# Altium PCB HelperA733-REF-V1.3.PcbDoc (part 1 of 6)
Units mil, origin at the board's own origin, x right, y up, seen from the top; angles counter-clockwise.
Board outline 5905.51 x 4133.86 mil, 2 copper layers (Top, Bottom), stack 12.7 mil thick; 446 components, 341 nets, 1706 pads, 1667 vias.
Unrouted connection lines stored in the file: 1382.
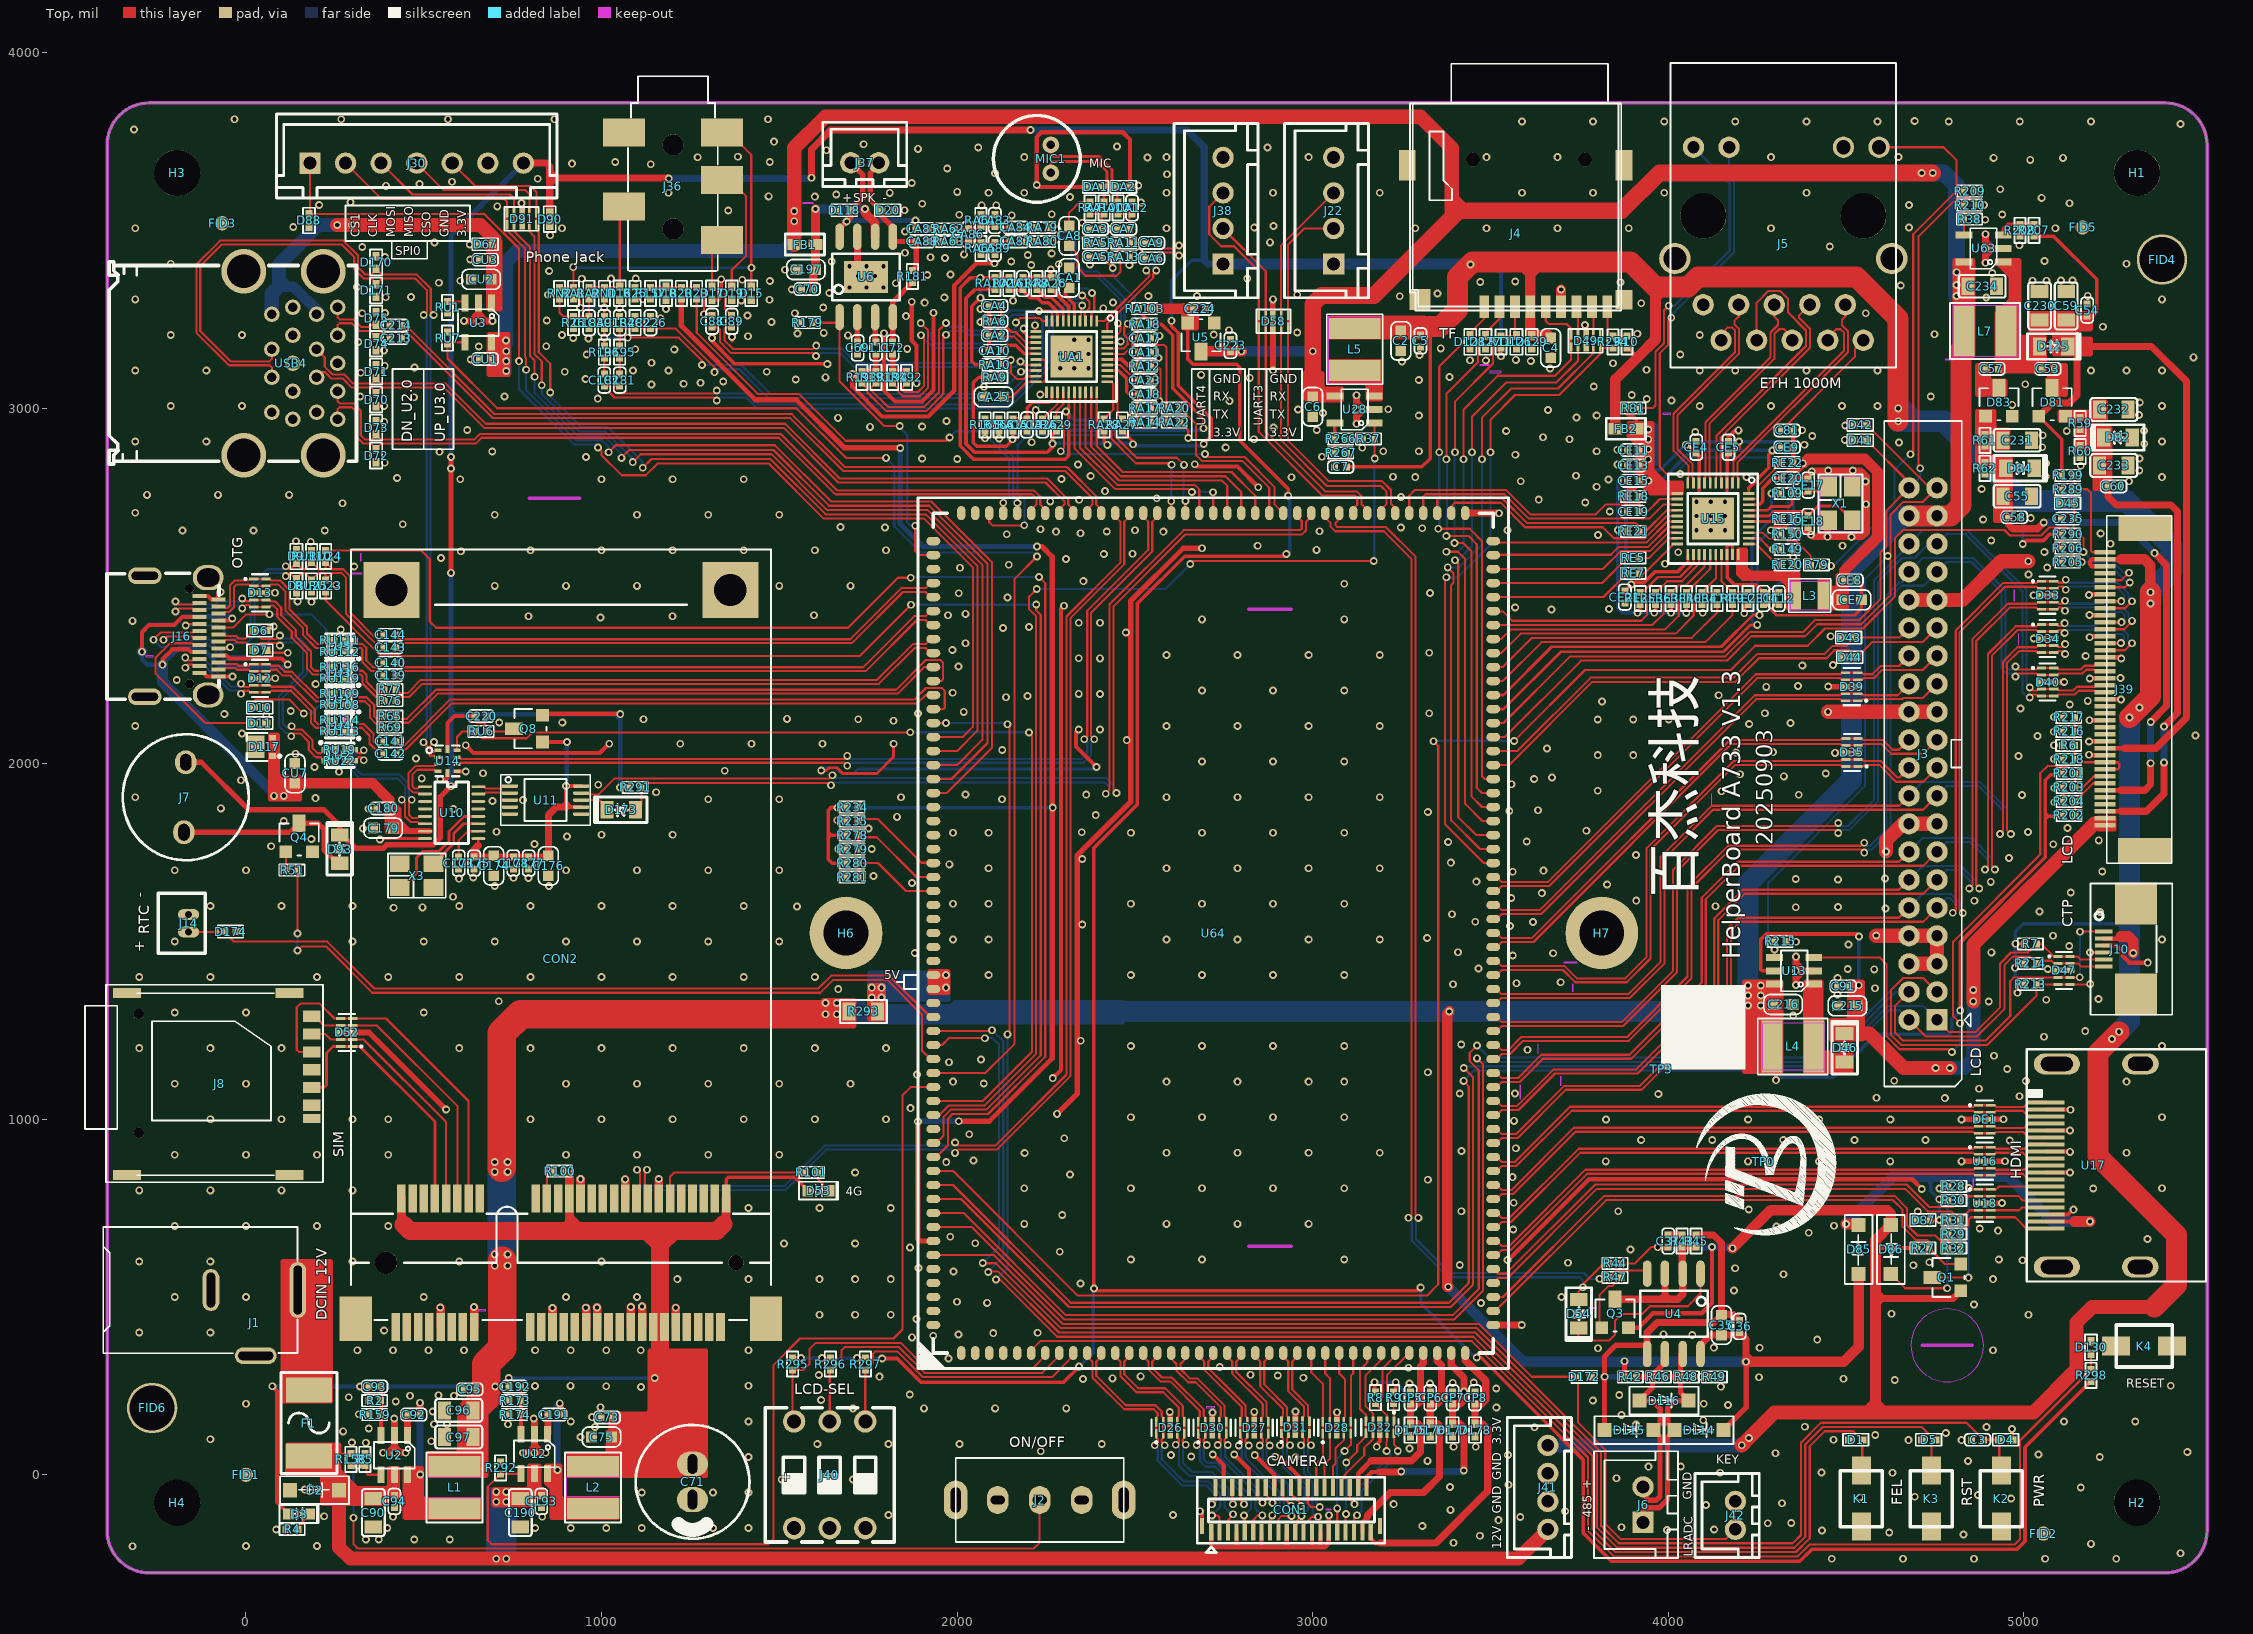
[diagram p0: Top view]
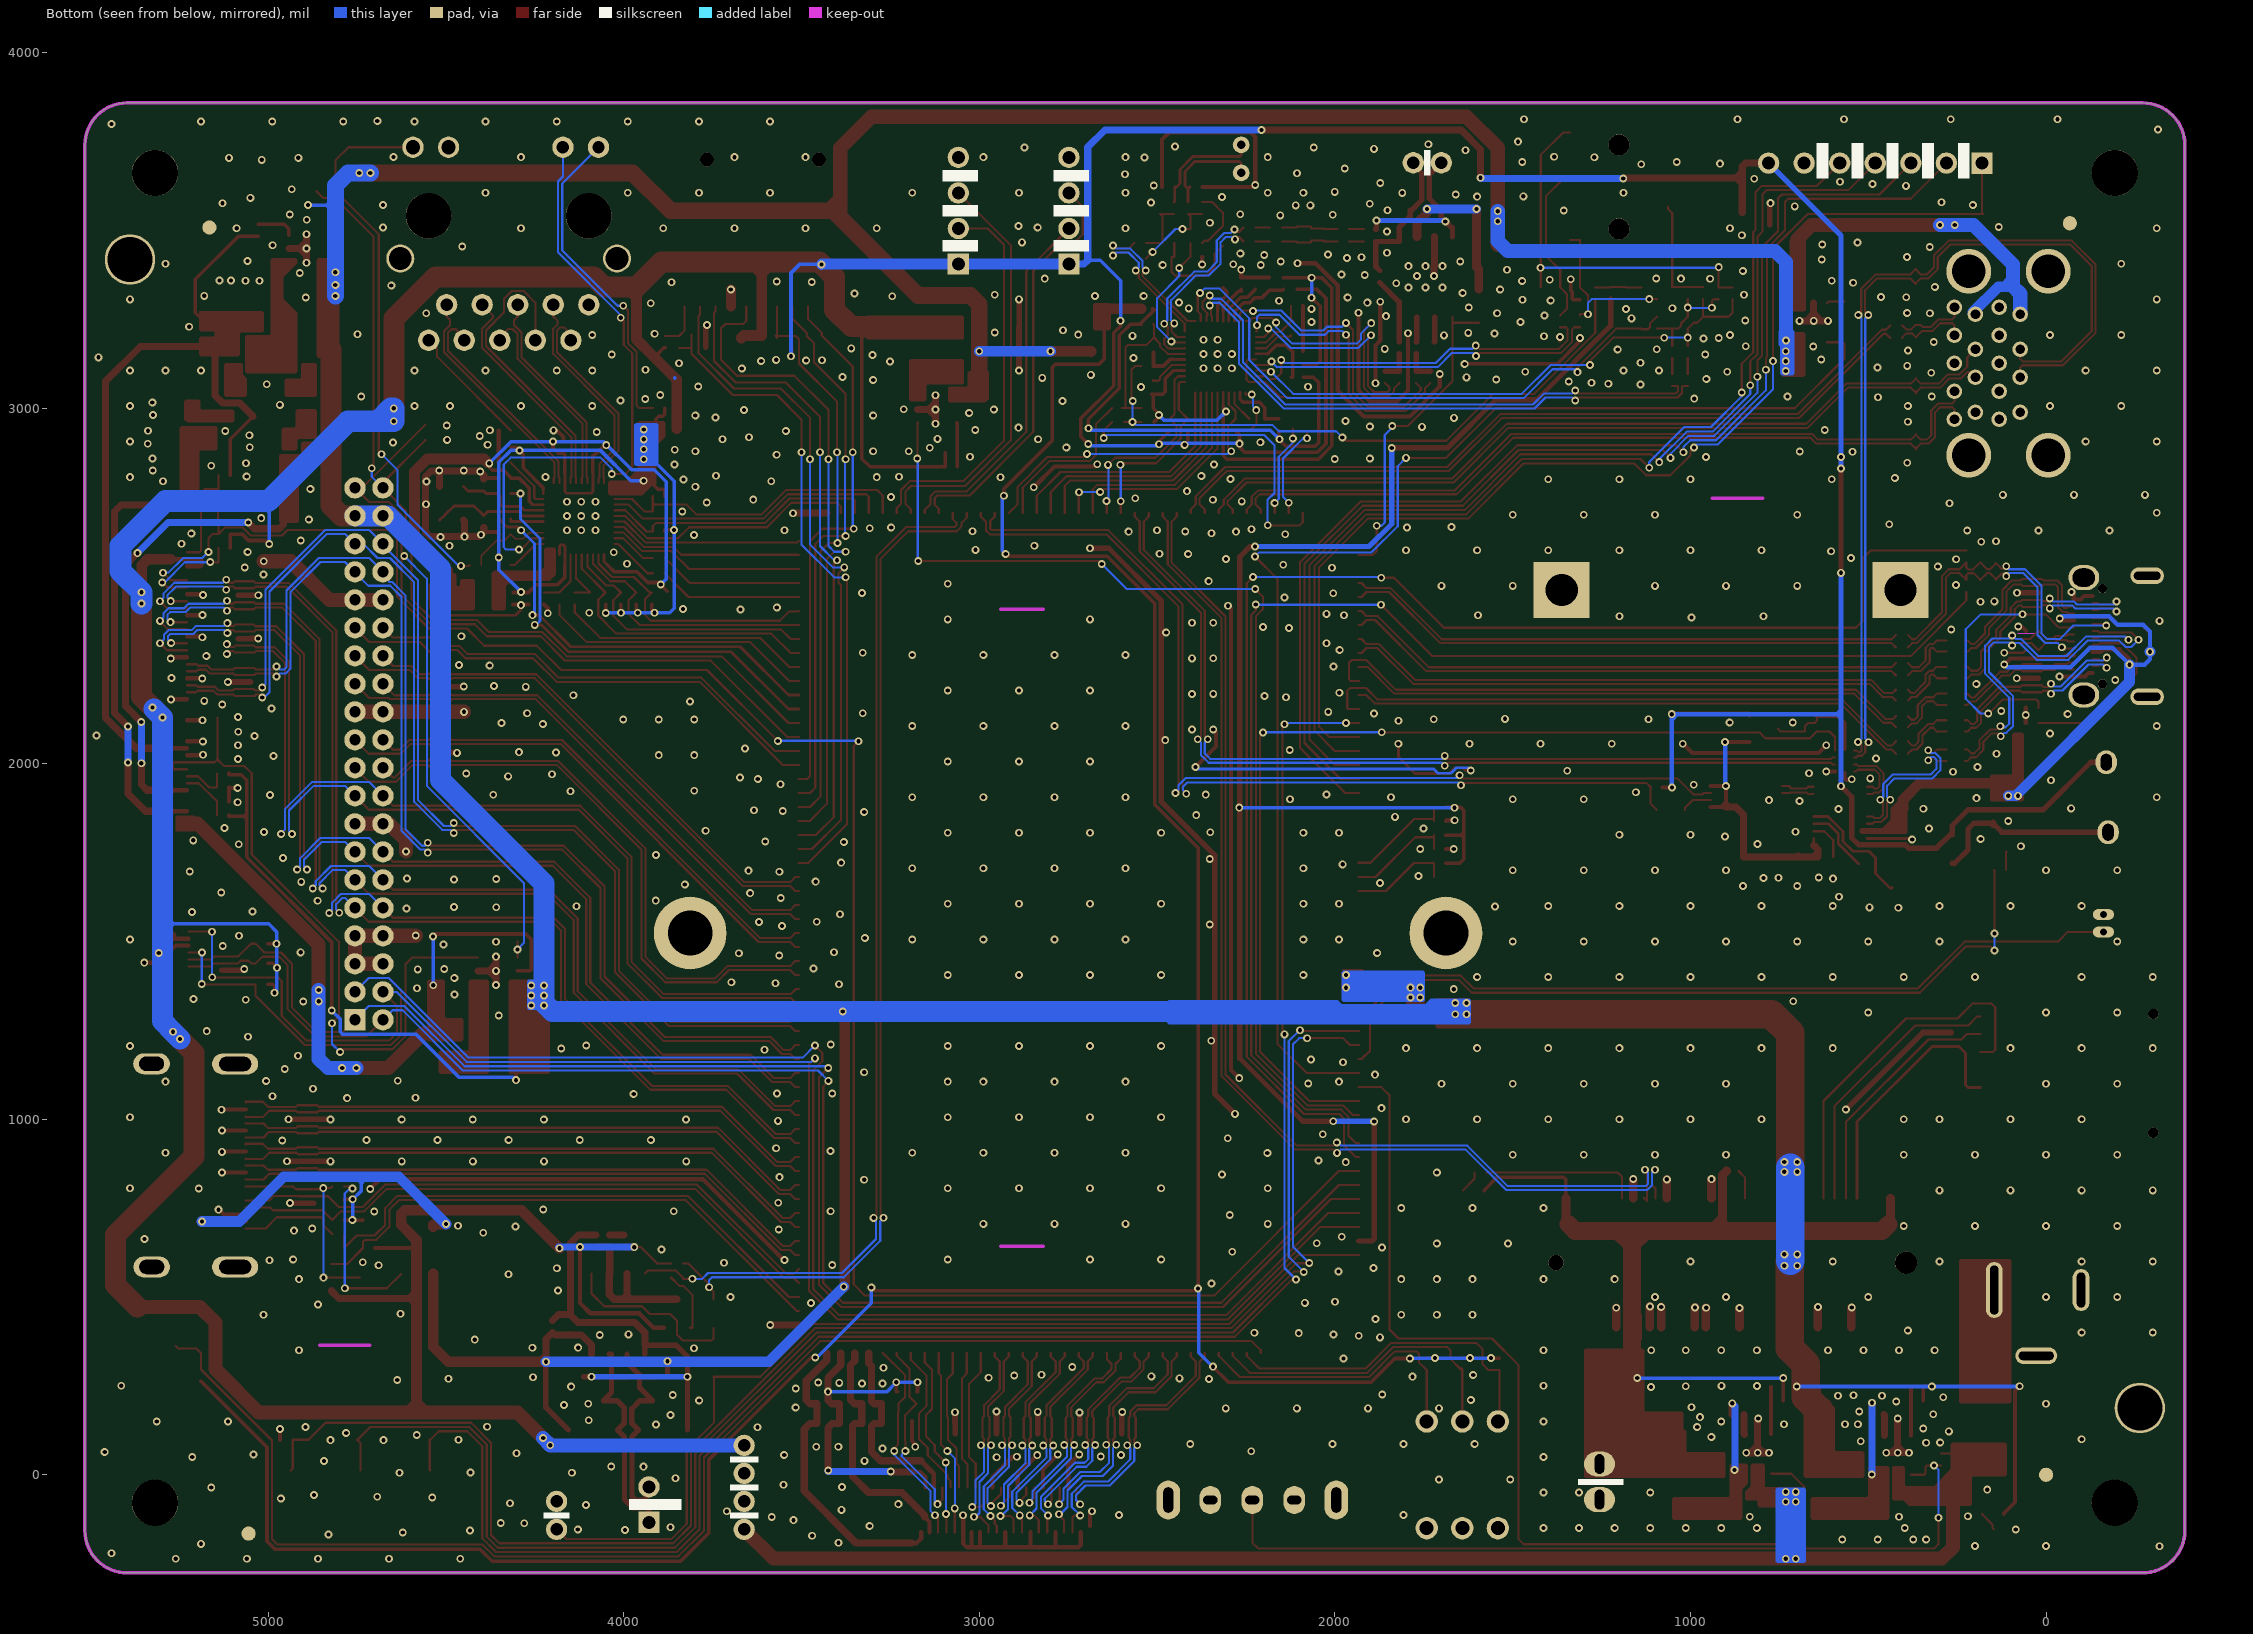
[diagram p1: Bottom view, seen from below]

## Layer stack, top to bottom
Solder Mask Top: solder mask 0.4, Solder Resist, Dk 3.5
Top: signal copper 1.35
Dielectric 1: dielectric 10, FR-4, Dk 4.3
Bottom: signal copper 1.35
Solder Mask Bottom: solder mask 0.4, Solder Resist, Dk 3.5

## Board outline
-390.17,3740.16 cw(c-272.06,3740.16) -272.06,3858.27 5397.23,3858.27 cw(c5397.23,3740.16) 5515.34,3740.16 5515.34,-157.48 cw(c5397.23,-157.48) 5397.23,-275.59 -272.06,-275.59 cw(c-272.06,-157.48) -390.17,-157.48

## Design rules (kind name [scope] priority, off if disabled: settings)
Clearance "Clearance - Net - 340_3V3" [InNet('340_3V3') OR InNet('LED1_AD1')] p1: gap=6 ignorepadtopadclearanceinfootprint=FALSE except(0: Arc-Hole Track-Hole SMDPad-Hole THPad-Hole Via-Hole Fill-Hole Poly-Hole Region-Hole Text-Hole; 10: Fill-Fill Fill-Poly Fill-Region Poly-Poly Poly-Region Region-Region Text-Text; 12: Arc-Fill Arc-Poly Arc-Region Track-Fill Track-Poly Track-Region SMDPad-Fill SMDPad-Poly SMDPad-Region THPad-Fill THPad-Poly THPad-Region Via-Fill Via-Poly Via-Region)
Clearance "Clearance - Net - GND" [InNet('GND')] p2: gap=6 ignorepadtopadclearanceinfootprint=FALSE except(0: Arc-Hole Track-Hole SMDPad-Hole THPad-Hole Via-Hole Fill-Hole Poly-Hole Region-Hole Text-Hole; 8: Arc-Fill Arc-Poly Arc-Region Track-Fill Track-Poly Track-Region SMDPad-Fill SMDPad-Poly SMDPad-Region THPad-Fill THPad-Poly THPad-Region Via-Fill Via-Poly Via-Region; 10: Fill-Fill Fill-Poly Fill-Region Poly-Poly Poly-Region Region-Region Text-Text)
Clearance "Clearance - Default - DEFAULT- SMD" [IsVia vs IsSMTPin] p3: gap=0 ignorepadtopadclearanceinfootprint=FALSE
Clearance "Clearance - Default - DEFAULT - Via" [IsVia vs IsVia] p4: gap=0 ignorepadtopadclearanceinfootprint=FALSE
Clearance "Clearance - Default - DEFAULT - Net" [All] p5: gap=6 ignorepadtopadclearanceinfootprint=FALSE except(0: Arc-Hole Track-Hole SMDPad-Hole THPad-Hole Via-Hole Fill-Hole Poly-Hole Region-Hole Text-Hole; 10: Fill-Fill Fill-Poly Fill-Region Poly-Poly Poly-Region Region-Region Text-Text)
ComponentClearance "ComponentClearance - Default - DEFAULT" [All] p1: gap=6 collisioncheckmode=3 verticalgap=10 showdistances=FALSE
FanoutControl Fanout_SOIC [IsSOIC] p1: bgadir=Out bgaviamode=Centered fanoutstyle=Auto fanoutdirection=Alternating viagrid=1 // Fanout_SOIC (Default Rule)
FanoutControl Fanout_Small [(CompPinCount < 5)] p2: bgadir=Out bgaviamode=Centered fanoutstyle=Auto fanoutdirection=OutThenIn viagrid=1 // Fanout_Small (Default Rule)
FanoutControl Fanout_LCC [IsLCC] p3: bgadir=Out bgaviamode=Centered fanoutstyle=Auto fanoutdirection=Alternating viagrid=1 // Fanout_LCC (Default Rule)
FanoutControl Fanout_BGA [IsBGA] p4: bgadir=Out bgaviamode=Centered fanoutstyle=Auto fanoutdirection=Alternating viagrid=1 // Fanout_BGA (Default Rule)
HoleToHoleClearance "HoleToHoleClearance - Default - DEFAULT" [All] p1: gap=6 allowstackedmicrovias=TRUE
Length "Length - NetClass - MLNetGroup4" [InNetClass('MLNetGroup4')] p1: maxlimit=18503.27 minlimit=0
Length "Default Length" [All] p2: maxlimit=50000 minlimit=0
MatchedLengths "MatchedLengths - NetClass - MLNetGroup4" [InNetClass('MLNetGroup4')] p1: tolerance=200 checknetsindiffpair=FALSE checkdiffpairvsdiffpair=TRUE checkxsignals=TRUE checkothers=TRUE
MaxMinImpedance "Default Impedance" [All] p1: minimum=50.00 maximum=150.0
ParallelSegment "Default Parallel Segment Same Layer" [All] p1: limit=1000 gap=200
ParallelSegment "Default Parallel Segment Adjasent" [All] p2: limit=1000 gap=200
PlaneConnect "Default PlaneConnect" [All] p1: planeconnectstyle=Relief reliefexpansion=20 reliefentries=0 reliefconductorwidth=15 reliefairgap=10
PolygonConnect "PolygonConnect - Default SMT" [IsSMTPin] p1: connectstyle=Relief reliefconductorwidth=10 reliefentries=4 polygonreliefangle="90 Angle" airgapwidth=10
PolygonConnect "PolygonConnect - Default Pad" [All] p2: connectstyle=Relief reliefconductorwidth=15 reliefentries=4 polygonreliefangle="45 Angle" airgapwidth=10
RoutingLayers "RoutingLayers - Default - DEFAULT" [All] p1: top layer_v5=TRUE bottom layer_v5=TRUE
RoutingPriority "RoutingPriority - Default - DEFAULT" [All] p1: routingpriority=3
RoutingTopology "Default Routing Topology" [All] p1: topology=Shortest
RoutingVias "RoutingVias - Default - DEFAULT" [All] p1: holewidth=12 width=22 viastyle="Through Hole" minholewidth=12 minwidth=22 maxholewidth=12 maxwidth=22
SMDToCorner "SMDToCorner - Default - DEFAULT" [All] p1: distance=0
SolderMaskExpansion [All] p1: expansion=4
Width "Width - Net - LED1_AD1" [InNet('LED1_AD1')] p1: maxlimit=200 minlimit=5 preferedwidth=5
Width "Width - Net - 340_3V3" [InNet('340_3V3')] p2: maxlimit=200 minlimit=5 preferedwidth=15
Width "Width - Net - GND" [InNet('GND')] p3: maxlimit=200 minlimit=5 preferedwidth=11.81
Width "Default Width" [All] p4: maxlimit=200 minlimit=6 preferedwidth=6
18 further rules are at their usual default settings.

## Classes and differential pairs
net class MLNetGroup4: LVDS0-D0N LVDS0-D0P LVDS0-D1N LVDS0-D1P LVDS0-D2N LVDS0-D2P
net class RoutingClass_9(RuleSet): 340_3V3 GND LED1_AD1

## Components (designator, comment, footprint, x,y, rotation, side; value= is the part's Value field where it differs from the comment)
C2 "C0603" C0603 3248.03,3188.98 r270 top
C3 "C0402" C0402 4870.08,98.43 r180 top
C4 "C0603" C0603 3669.29,3169.29 r90 top
C5 "C0402" C0402 3303.15,3188.98 r270 top
C6 "C0603" C0603 3000,3003.94 r270 top
C7 "C0402" C0402 3078.74,2834.65 r180 top
C35 "C0603" C0603 4149.61,421.26 r90 top
C36 "C0402" C0402 4200.79,417.32 r90 top
C37 "C0402" C0402 4000,657.48 r90 top
C53 "C0402" C0402 5067.91,3110.24 r180 top
C54 "C0402" C0402 5178.15,3275.59 r90 top
C55 "C0805" C0805 4981.3,2751.97 r0 top
C57 "C0402" C0402 4910.43,3110.24 r180 top
C58 "C0402" C0402 4973.42,2692.91 r0 top
C59 "C0805" C0805 5119.09,3287.4 r90 top
C60 "C0402" C0402 5252.95,2779.53 r0 top
C69 "C0402" C0402 1720.47,3169.29 r270 top
C70 "C0402" C0402 1578.74,3334.65 r180 top
C71 "RB.1$2F$.3" RB.1$2F$.3 1255.91,-19.68 r90 top
C72 "C0402" C0402 1818.9,3169.29 r270 top
C73 "C0402" C0402 1015.75,161.42 r180 top
C75 "C0603" C0603 1000,106.3 r180 top
C81 "C0402" C0402 4334.65,2937.01 r180 top
C88 "C0402" C0402 1311.02,3244.09 r270 top
C89 "C0402" C0402 1366.14,3244.09 r270 top
C90 "C0805" C0805 358.27,-106.3 r270 top
C91 "C0402" C0402 4492.13,1374.02 r180 top
C92 "C0402" C0402 472.44,169.29 r0 top
C93 "C0402" C0402 362.2,248.03 r0 top
C94 "C0402" C0402 417.32,-74.8 r270 top
C95 "C0402" C0402 629.92,240.16 r180 top
C96 "C0805" C0805 598.43,181.1 r180 top
C97 "C0805" C0805 598.43,106.3 r180 top
C111 "C0402" C0402 1771.65,3169.29 r270 top
C139 "C0402" C0402 405.51,2248.03 r180 top
C140 "C0402" C0402 405.51,2283.46 r180 top
C141 "C0402" C0402 405.51,2062.99 r180 top
C142 "C0402" C0402 405.51,2027.56 r180 top
C143 "C0402" C0402 405.51,2326.77 r180 top
C144 "C0402" C0402 405.51,2362.2 r180 top
C173 "C0402" C0402 598.43,1720.47 r270 top
C174 "C0603" C0603 696.85,1712.6 r270 top
C175 "C0402" C0402 641.73,1720.47 r270 top
C176 "C0603" C0603 850.39,1712.6 r270 top
C177 "C0402" C0402 795.28,1720.47 r270 top
C178 "C0402" C0402 751.97,1720.47 r270 top
C179 "C0603" C0603 385.83,1818.9 r180 top
C180 "C0402" C0402 385.83,1874.02 r180 top
C181 "C0402" C0402 1051.18,3078.74 r90 top
C182 "C0402" C0402 1007.87,3078.74 r90 top
C183 "C0402" C0402 964.57,3240.16 r270 top
C184 "C0402" C0402 1051.18,3240.16 r90 top
C190 "C0805" C0805 771.65,-106.3 r270 top
C191 "C0402" C0402 866.14,169.29 r0 top
C192 "C0402" C0402 755.91,248.03 r0 top
C193 "C0402" C0402 830.71,-74.8 r270 top
C197 "C0603" C0603 1574.8,3389.76 r180 top
C213 "C0402" C0402 421.38,3197.01 r180 top
C214 "C0402" C0402 421.38,3232.44 r180 top
C215 "C0603" C0603 4503.94,1318.9 r180 top
C216 "C0603" C0603 4322.83,1322.83 r0 top
C220 "C0402" C0402 661.42,2133.86 r0 top
C223 "C0402" C0402 2768.64,3176.34 r270 top
C224 "C0402" C0402 2682.02,3278.7 r180 top
C226 "C0402" C0402 1137.8,3240.16 r270 top
C230 "C0805" C0805 5044.29,3287.4 r90 top
C231 "C0805" C0805 4981.3,2909.45 r180 top
C232 "C0805" C0805 5252.95,2996.06 r0 top
C233 "C0805" C0805 5252.95,2838.58 r0 top
C234 "C0805" C0805 4882.87,3342.52 r0 top
C235 "C0402" C0402 5123.03,2688.98 r0 top
CA1 "C0603" C0603 2314.96,3366.14 r270 top
CA2 "C0402" C0402 2106.3,3204.72 r180 top
CA3 "C0402" C0402 2389.76,3503.94 r0 top
CA4 "C0402" C0402 2106.3,3287.4 r0 top
CA5 "C0402" C0402 2389.76,3425.2 r0 top
CA6 "C0402" C0402 2547.24,3421.26 r180 top
CA7 "C0402" C0402 2468.5,3503.94 r0 top
CA8 "C0603" C0603 2314.96,3484.25 r270 top
CA9 "C0402" C0402 2547.24,3464.57 r180 top
CA10 "C0402" C0402 2106.3,3161.42 r180 top
CA11 "C0402" C0402 2527.56,3157.48 r0 top
CA12 "C0402" C0402 2492.13,3562.99 r90 top
CA13 "C0402" C0402 2196.85,2952.76 r270 top
CA14 "C0402" C0402 2185.04,3350.39 r90 top
CA17 "C0402" C0402 2527.56,3196.85 r0 top
CA18 "C0402" C0402 2527.56,3039.37 r180 top
CA23 "C0402" C0402 2527.56,3078.74 r0 top
CA25 "C0603" C0603 2102.36,3031.5 r180 top
CA26 "C0402" C0402 2240.16,2952.76 r270 top
CA83 "C0402" C0402 2106.3,3527.56 r270 top
CA84 "C0402" C0402 2165.35,3507.87 r0 top
CA85 "C0402" C0402 1901.57,3503.94 r0 top
CA86 "C0402" C0402 2031.5,3488.19 r270 top
CA87 "C0402" C0402 2165.35,3468.5 r0 top
CA88 "C0402" C0402 1901.57,3468.5 r0 top
CA89 "C0402" C0402 2106.3,3448.82 r270 top
CA91 "C0402" C0402 1007.87,3240.16 r270 top
CE4 "C0402" C0402 4078.74,2889.76 r270 top
CE5 "C0402" C0402 4169.29,2889.76 r270 top
CE7 "C0603" C0603 4515.75,2460.63 r180 top
CE8 "C0402" C0402 4511.81,2515.75 r180 top
CE9 "C0402" C0402 4334.65,2889.76 r180 top
CE11 "C0402" C0402 3901.57,2881.89 r0 top
CE12 "C0402" C0402 4311.02,2464.57 r90 top
CE13 "C0402" C0402 3901.57,2838.58 r0 top
CE14 "C0402" C0402 4267.72,2464.57 r90 top
CE15 "C0402" C0402 3901.57,2795.28 r0 top
CE17 "C0402" C0402 4393.7,2783.46 r270 top
CE18 "C0402" C0402 4393.7,2681.1 r90 top
CE19 "C0402" C0402 3901.57,2708.66 r0 top
CE20 "C0402" C0402 4334.65,2803.15 r180 top
CE21 "C0402" C0402 3877.95,2468.5 r90 top
CON1 "FH35C-39S-0.3SHW" FH35C-39S-0.3SHW 2939.1,-102.33 r0 top
CON2 "MINI_PCIEX1-52P-5.2H" MINI_PCIEX1-52P-5.2H 885.83,1627.03 r0 top
CP5 "C0402" C0402 3275.59,216.54 r90 top
CP6 "C0402" C0402 3330.71,216.54 r90 top
CP7 "C0402" C0402 3393.7,216.54 r90 top
CP8 "C0402" C0402 3456.69,216.54 r90 top
CU1 "C0402" C0402 673.23,3137.8 r0 top
CU2 "C0603" C0603 661.42,3362.2 r0 top
CU3 "C0402" C0402 673.23,3417.32 r0 top
CU7 "C0603" C0603 137.8,1972.44 r90 top
D1 "ESD0402" ESD0402 4527.56,98.43 r180 top
D2 "SOD123" SOD123 192.91,-43.31 r0 top
D3 "D0603" D0603 149.61,-110.24 r0 top
D4 "ESD0402" ESD0402 4948.82,98.43 r180 top
D5 "ESD0402" ESD0402 4732.28,98.43 r0 top
D6 "ESD0402" ESD0402 39.37,2374.02 r0 top
D7 "ESD0402" ESD0402 39.37,2318.9 r0 top
D8 "ESD0402" ESD0402 141.73,2500 r270 top
D9 "ESD0402" ESD0402 141.73,2582.68 r90 top
D10 "ESD0402" ESD0402 39.37,2157.48 r0 top
D11 "ESD0402" ESD0402 39.37,2114.17 r0 top
D12 "DFN2510-10_L2.5-W1.0-P0.50-BL" DFN2510-10_L2.5-W1.0-P0.50-BL 39.37,2240.16 r270 top
D13 "DFN2510-10_L2.5-W1.0-P0.50-BL" DFN2510-10_L2.5-W1.0-P0.50-BL 39.37,2480.32 r270 top
D15 "ESD0402" ESD0402 1421.26,3322.83 r90 top
D16 "ESD0402" ESD0402 1051.18,3322.83 r90 top
D17 "ESD0402" ESD0402 1311.02,3322.83 r90 top
D18 "ESD0402" ESD0402 1181.1,3322.83 r90 top
D19 "ESD0402" ESD0402 1366.14,3322.83 r90 top
D20 "ESD0402" ESD0402 1805.07,3556.24 r180 top
D26 "DFN2510-10_L2.5-W1.0-P0.50-BL" DFN2510-10_L2.5-W1.0-P0.50-BL 2599.43,132.32 r0 top
D27 "DFN2510-10_L2.5-W1.0-P0.50-BL" DFN2510-10_L2.5-W1.0-P0.50-BL 2835.65,132.32 r0 top
D28 "DFN2510-10_L2.5-W1.0-P0.50-BL" DFN2510-10_L2.5-W1.0-P0.50-BL 3067.94,132.32 r0 top
D30 "DFN2510-10_L2.5-W1.0-P0.50-BL" DFN2510-10_L2.5-W1.0-P0.50-BL 2717.54,132.32 r0 top
D31 "DFN2510-10_L2.5-W1.0-P0.50-BL" DFN2510-10_L2.5-W1.0-P0.50-BL 2951.48,133.21 r0 top
D32 "DFN2510-10_L2.5-W1.0-P0.50-BL" DFN2510-10_L2.5-W1.0-P0.50-BL 3188.98,133.86 r180 top
D33 "DFN2510-10_L2.5-W1.0-P0.50-BL" DFN2510-10_L2.5-W1.0-P0.50-BL 5066.93,2473.73 r270 top
D34 "DFN2510-10_L2.5-W1.0-P0.50-BL" DFN2510-10_L2.5-W1.0-P0.50-BL 5066.93,2351.69 r270 top
D35 "DFN2510-10_L2.5-W1.0-P0.50-BL" DFN2510-10_L2.5-W1.0-P0.50-BL 4516.73,2031.5 r90 top
D39 "DFN2510-10_L2.5-W1.0-P0.50-BL" DFN2510-10_L2.5-W1.0-P0.50-BL 4515.75,2216.54 r90 top
D40 "DFN2510-10_L2.5-W1.0-P0.50-BL" DFN2510-10_L2.5-W1.0-P0.50-BL 5066.93,2229.64 r270 top
D41 "ESD0402" ESD0402 4540.35,2909.45 r180 top
D42 "ESD0402" ESD0402 4540.35,2952.76 r180 top
D43 "ESD0402" ESD0402 4507.87,2354.33 r180 top
D44 "ESD0402" ESD0402 4510.9,2299.12 r180 top
D45 "ESD0402" ESD0402 5123.03,2732.28 r180 top
D46 "SOD323" SOD323 4496.06,1200.79 r90 top
D47 "DFN2510-10_L2.5-W1.0-P0.50-BL" DFN2510-10_L2.5-W1.0-P0.50-BL 5112.97,1418.57 r270 top
D49 "RCLAMP0524P" RCLAMP0524P 3767.72,3188.98 r180 top
D52 "DFN2510-10_L2.5-W1.0-P0.50-BL" DFN2510-10_L2.5-W1.0-P0.50-BL 283.46,1244.09 r90 top
D53 "D0603" D0603 1610.24,799.21 r0 top
D54 "SOD323" SOD323 3748.03,452.76 r270 top
D58 "RCLAMP0524P" RCLAMP0524P 2889.76,3244.09 r0 top
D67 "ESD0402" ESD0402 673.23,3460.63 r0 top
D70 "ESD0402" ESD0402 366.26,3023.78 r270 top
D71 "ESD0402" ESD0402 366.26,3102.52 r90 top
D72 "ESD0402" ESD0402 366.26,2866.3 r270 top
D73 "ESD0402" ESD0402 366.26,2945.04 r90 top
D74 "ESD0402" ESD0402 366.26,3181.26 r270 top
D75 "ESD0402" ESD0402 366.26,3252.13 r90 top
D81 "SOT23" SOT23 5079.72,3015.75 r0 top
D82 "D0805" D0805 5264.76,2917.32 r180 top
D83 "SOT23" SOT23 4930.12,3015.75 r0 top
D84 "D0805" D0805 4989.17,2830.71 r0 top
D85 "SOD123" SOD123 4535.43,633.86 r90 top
D86 "SOD123" SOD123 4625.98,633.86 r270 top
D87 "ESD0402" ESD0402 4716.54,716.54 r180 top
D88 "ESD0402" ESD0402 177.17,3527.56 r270 top
D90 "ESD0402" ESD0402 854.33,3531.5 r270 top
D91 "RCLAMP0524P" RCLAMP0524P 775.41,3532.11 r180 top
D93 "SOD323" SOD323 263.78,1759.84 r90 top
D114 "SOD123" SOD123 4086.61,125.98 r0 top
D115 "SOD123" SOD123 3889.76,125.98 r0 top
D116 "SOD123" SOD123 3988.19,208.66 r0 top
D117 "DFN-3_2X2" DFN-3_2X2 51.18,2047.24 r0 top
D118 "ESD0402" ESD0402 1683.02,3556.24 r0 top
D125 "D0805" D0805 5083.66,3173.23 r0 top
D126 "ESD0402" ESD0402 3572.95,3186.09 r90 top
D127 "ESD0402" ESD0402 3486.34,3186.09 r90 top
D128 "ESD0402" ESD0402 3443.03,3186.09 r90 top
D129 "ESD0402" ESD0402 3616.26,3186.09 r90 top
D130 "ESD0402" ESD0402 5188.98,358.27 r90 top
D170 "ESD0402" ESD0402 366.26,3409.61 r90 top
D171 "ESD0402" ESD0402 366.26,3330.87 r270 top
D172 "ESD0402" ESD0402 3763.78,275.59 r180 top
D173 "SOD323" SOD323 1055.12,1870.08 r180 top
D174 "ESD0402" ESD0402 -43.31,1527.56 r180 top
D175 "ESD0402" ESD0402 3275.59,125.98 r90 top
D176 "ESD0402" ESD0402 3330.71,125.98 r90 top
D177 "ESD0402" ESD0402 3393.7,125.98 r90 top
D178 "ESD0402" ESD0402 3456.69,125.98 r90 top
DA1 "ESD0402" ESD0402 2389.76,3622.05 r0 top
DA2 "ESD0402" ESD0402 2468.5,3622.05 r180 top
DE1 "DFN2510-10_L2.5-W1.0-P0.50-BL" DFN2510-10_L2.5-W1.0-P0.50-BL 4889.76,1000 r270 top
F1 "F1812" F1812 177.17,145.67 r270 top
FB1 "L0603" L0603 1602.36,3460.63 r180 top
FB2 "L0603" L0603 3850.39,2940.94 r0 top
FID1 "MARK" MARK 0,0 r270 top
FID2 "MARK" MARK 5055.12,-165.35 r0 top
FID3 "MARK" MARK -66.93,3519.69 r0 top
FID4 "DVE" DVE 5388.69,3417.75 r0 top
FID5 "MARK" MARK 5165.35,3507.87 r0 top
FID6 "DVE" DVE -263.84,188.01 r0 top
H1 "DVA" DVA 5318.49,3661.42 r0 top
H2 "DVA" DVA 5318.49,-78.74 r0 top
H3 "DVA" DVA -193.32,3661.42 r0 top
H4 "DVA" DVA -193.32,-78.74 r0 top
H6 "DV" DV 1687.91,1523.62 r0 top
H7 "DV" DV 3813.29,1523.62 r0 top
J1 "DC470" DC470 -98.43,519.69 r0 top
J2 "SS-12F44(1P2T)" SS-12F44(1P2T) 2232.28,-70.87 r0 top
J3 "HDR2X20$2F$2.0" HDR2X20$2F$2.0 4755.91,1279.53 r90 top
J4 "TF_PUSH1" TF_PUSH1 3570.87,3570.87 r0 top
J5 "HY911130A" HY911130A 4548.61,3190.72 r0 top
J6 "XH-2.54-2P" XH-2.54-2P 3929.13,-133.86 r90 top
J7 "BEEP_9042" BEEP_9042 -169.29,1905.51 r270 top
J8 "NANO-SIM-7P" NANO-SIM-7P -86.61,1098.43 r270 top
J10 "FPC_0.5_6P_DOWN" FPC_0.5_6P_DOWN 5224.41,1527.56 r270 top
J14 "MX1.25-2P" MX1.25-2P -161.42,1551.18 r270 top
J16 "USB-C-SMD-24P" USB-C-SMD-24P -181.1,2358.27 r270 top
J22 "XH-2.54-4P" XH-2.54-4P 3059.06,3555.12 r270 top
J30 "XH-2.54-7P" XH-2.54-7P 480.31,3688.98 r180 top
J36 "PJ327F" PJ327F 1082.68,3858.27 r270 top
J37 "PH-2.0-2P" PH-2.0-2P 1700.81,3689.85 r0 top
J38 "XH-2.54-4P" XH-2.54-4P 2748.03,3555.12 r270 top
J39 "FPC40-0.5MM-UP" FPC40-0.5MM-UP 5208.66,1826.77 r90 top
J40 "SW-TH-DSWB03LHGET" SW-TH-DSWB03LHGET 1641.73,0 r0 top
J41 "PH-2.0-4P" PH-2.0-4P 3661.42,-153.54 r90 top
J42 "PH-2.0-2P" PH-2.0-2P 4188.98,-153.54 r90 top
K1 "KEY_3X4" KEY_3X4 4543.31,-66.93 r270 top
K2 "KEY_3X4" KEY_3X4 4937.01,-66.93 r90 top
K3 "KEY_3X4" KEY_3X4 4740.16,-66.93 r90 top
K4 "KEY_3X4" KEY_3X4 5338.58,362.2 r0 top
L1 "4018" 4018 586.61,-35.43 r90 top
L2 "4018" 4018 976.38,-35.43 r90 top
L3 "SML2520_1P2H$2F$4" SML2520_1P2H$2F$4 4397.64,2472.44 r270 top
L4 "4018" 4018 4350.39,1204.72 r0 top
L5 "4018" 4018 3118.11,3165.35 r90 top
L7 "4018" 4018 4890.75,3216.54 r0 top
LU1 "0805" 0805 263.78,2181.1 r90 top
LU2 "0805" 0805 263.78,2023.62 r270 top
LU3 "0805" 0805 263.78,2255.91 r90 top
LU4 "0805" 0805 263.78,2106.3 r90 top
LU5 "0805" 0805 263.78,2330.71 r90 top
MIC1 "MIC6050" MIC6050 2224.41,3700.79 r0 top
Q1 "SOT23" SOT23 4783.46,555.12 r90 top
Q3 "SOT23" SOT23 3850.39,452.76 r0 top
Q4 "SOT23" SOT23 149.61,1791.34 r0 top
Q8 "SOT23" SOT23 795.28,2098.43 r90 top
R2 "R0402" R0402 362.2,208.66 r0 top
R4 "R0402" R0402 129.92,-153.54 r0 top
R5 "R0402" R0402 334.65,43.31 r90 top
R6 "R0402" R0402 5125.98,2051.18 r180 top
R7 "R0402" R0402 5018.48,1493.37 r180 top
R8 "R0402" R0402 3176.54,216.76 r270 top
R9 "R0402" R0402 3227.72,216.76 r270 top
R10 "R0402" R0402 3883.97,3186.09 r90 top
R11 "R0402" R0402 3529.64,3186.09 r90 top
R20 "R0402" R0402 1224.41,3322.83 r90 top
R23 "R0402" R0402 1267.72,3322.83 r90 top
R25 "R0402" R0402 1094.49,3322.83 r90 top
R26 "R0402" R0402 921.26,3240.16 r270 top
R27 "R0402" R0402 4716.54,637.8 r180 top
R28 "R0402" R0402 4803.15,811.02 r0 top
R29 "R0402" R0402 4803.15,677.17 r0 top
R30 "R0402" R0402 4803.15,771.65 r180 top
R31 "R0402" R0402 4803.15,716.54 r180 top
R32 "R0402" R0402 4803.15,637.8 r0 top
R37 "R0402" R0402 3157.48,2913.39 r0 top
R38 "R0402" R0402 4847.44,3531.5 r180 top
R42 "R0402" R0402 3893.7,275.59 r0 top
R43 "R0402" R0402 4039.37,657.48 r270 top
R44 "R0402" R0402 3850.39,594.49 r0 top
R45 "R0402" R0402 4078.74,657.48 r90 top
R46 "R0402" R0402 3972.44,275.59 r180 top
R47 "R0402" R0402 3850.39,555.12 r180 top
R48 "R0402" R0402 4051.18,275.59 r180 top
R49 "R0402" R0402 4129.92,275.59 r0 top
R51 "R0402" R0402 129.92,1700.79 r180 top
R59 "R0402" R0402 5158.46,2956.69 r270 top
R60 "R0402" R0402 5158.46,2877.95 r90 top
R61 "R0402" R0402 4890.75,2909.45 r270 top
R62 "R0402" R0402 4890.75,2830.71 r90 top
R65 "R0402" R0402 405.51,2133.86 r180 top
R69 "R0402" R0402 405.51,2102.36 r180 top
R76 "R0402" R0402 405.51,2177.17 r180 top
R77 "R0402" R0402 405.51,2208.66 r180 top
R79 "R0402" R0402 4417.32,2559.06 r180 top
R81 "R0402" R0402 3901.57,3000 r180 top
R100 "R0402" R0402 881.89,854.33 r0 top
R101 "R0402" R0402 1590.55,850.39 r0 top
R109 "R0402" R0402 4334.65,2759.84 r0 top
R149 "R0402" R0402 4334.65,2602.36 r180 top
R150 "R0402" R0402 4334.65,2645.67 r180 top
R157 "R0402" R0402 1137.8,3322.83 r270 top
R158 "R0402" R0402 295.28,43.31 r270 top
R159 "R0402" R0402 362.2,169.29 r180 top
R165 "R0402" R0402 2078.74,2952.76 r270 top
R166 "R0402" R0402 2118.11,2952.76 r270 top
R173 "R0402" R0402 755.91,208.66 r0 top
R174 "R0402" R0402 755.91,169.29 r180 top
R179 "R0402" R0402 1578.74,3240.16 r0 top
R181 "R0402" R0402 1874.02,3370.08 r90 top
R191 "R0402" R0402 1771.65,3086.61 r90 top
R192 "R0402" R0402 1858.27,3086.61 r90 top
R193 "R0402" R0402 1732.28,3086.61 r90 top
R194 "R0402" R0402 1818.9,3086.61 r90 top
R195 "R0402" R0402 1051.18,3157.48 r90 top
R196 "R0402" R0402 1007.87,3157.48 r90 top
R199 "R0402" R0402 5123.03,2811.02 r0 top
R201 "R0402" R0402 5126.97,1972.44 r0 top
R202 "R0402" R0402 5126.97,1854.33 r0 top
R203 "R0402" R0402 5126.97,1933.07 r180 top
R204 "R0402" R0402 5126.97,1893.7 r180 top
R205 "R0402" R0402 5123.03,2566.93 r180 top
R206 "R0402" R0402 5123.03,2606.3 r0 top
R207 "R0402" R0402 5028.54,3500 r270 top
R208 "R0402" R0402 4989.17,3500 r270 top
R209 "R0402" R0402 4847.44,3610.24 r180 top
R210 "R0402" R0402 4847.44,3570.87 r0 top
R213 "R0402" R0402 5018.48,1379.2 r180 top
R214 "R0402" R0402 5018.48,1438.25 r180 top
R215 "R0402" R0402 4314.96,1500 r0 top
R216 "R0402" R0402 5125.98,2090.55 r180 top
R217 "R0402" R0402 5125.98,2129.92 r180 top
R218 "R0402" R0402 5125.98,2011.81 r180 top
R234 "R0402" R0402 1704.72,1877.95 r0 top
R235 "R0402" R0402 1704.72,1838.58 r180 top
R266 "R0402" R0402 3078.74,2913.39 r0 top
R267 "R0402" R0402 3078.74,2874.02 r180 top
R278 "R0402" R0402 1704.72,1799.21 r0 top
R279 "R0402" R0402 1704.72,1759.84 r180 top
R280 "R0402" R0402 1704.72,1720.47 r0 top
R281 "R0402" R0402 1704.72,1681.1 r180 top
R282 "R0402" R0402 1094.49,3240.16 r90 top
R289 "R0402" R0402 5123.03,2771.65 r180 top
R290 "R0402" R0402 5123.03,2645.67 r0 top
R291 "R0402" R0402 1094.49,1933.07 r180 top
R292 "R0402" R0402 716.54,19.69 r90 top
R293 "R0805" R0805 1736.22,1303.15 r0 top
R294 "R0402" R0402 3844.6,3186.09 r90 top
R295 "R0402" R0402 1537.49,311.58 r270 top
R296 "R0402" R0402 1643.79,311.58 r270 top
R297 "R0402" R0402 1742.21,311.58 r270 top
R298 "R0402" R0402 5188.98,279.53 r90 top
RA1 "R0402" R0402 921.26,3322.83 r90 top
RA2 "R0402" R0402 964.57,3322.83 r90 top
RA5 "R0402" R0402 2389.76,3464.57 r0 top
RA6 "C0402" C0402 2106.3,3244.09 r0 top
RA7 "R0402" R0402 2374.02,3562.99 r270 top
RA8 "R0402" R0402 2224.41,3350.39 r90 top
RA9 "R0402" R0402 2106.3,3086.61 r0 top
RA10 "R0402" R0402 2106.3,3122.05 r180 top
RA11 "R0402" R0402 2468.5,3464.57 r0 top
RA12 "R0402" R0402 2527.56,3118.11 r0 top
RA13 "R0402" R0402 2468.5,3425.2 r0 top
RA14 "R0402" R0402 2527.56,2960.63 r0 top
RA15 "R0402" R0402 2157.48,2952.76 r90 top
RA16 "R0402" R0402 2145.67,3350.39 r270 top
RA17 "R0402" R0402 2527.56,3000 r180 top
RA18 "R0402" R0402 2527.56,3236.22 r180 top
RA20 "R0402" R0402 2610.24,3000 r0 top
RA22 "R0402" R0402 2610.24,2960.63 r0 top
RA26 "R0402" R0402 2263.78,3350.39 r90 top
RA27 "R0402" R0402 2464.57,2952.76 r270 top
RA28 "R0402" R0402 2413.39,2952.76 r270 top
RA29 "R0402" R0402 2279.53,2952.76 r90 top
RA61 "R0402" R0402 2066.93,3527.56 r90 top
RA62 "R0402" R0402 1976.38,3503.94 r0 top
RA63 "R0402" R0402 1976.38,3468.5 r0 top
RA65 "R0402" R0402 2066.93,3448.82 r90 top
RA79 "R0402" R0402 2240.16,3507.87 r0 top
RA80 "R0402" R0402 2240.16,3468.5 r0 top
RA100 "R0402" R0402 2413.39,3562.99 r270 top
RA101 "R0402" R0402 2452.76,3562.99 r270 top
RA102 "R0402" R0402 2106.3,3350.39 r90 top
RA103 "R0402" R0402 2527.56,3279.53 r180 top
RE5 "R0402" R0402 3901.57,2578.74 r0 top
RE7 "R0402" R0402 3901.57,2535.43 r0 top
RE9 "R0402" R0402 4181.1,2464.57 r90 top
RE14 "R0402" R0402 4137.8,2464.57 r90 top
RE15 "R0402" R0402 4334.65,2688.98 r180 top
RE18 "R0402" R0402 3901.57,2751.97 r0 top
RE20 "R0402" R0402 4334.65,2559.06 r180 top
RE21 "R0402" R0402 3901.57,2653.54 r0 top
RE22 "R0402" R0402 4334.65,2846.46 r180 top
RE23 "R0402" R0402 4224.41,2464.57 r90 top
RE25 "R0402" R0402 3921.26,2464.57 r270 top
RE34 "R0402" R0402 4094.49,2464.57 r90 top
RE36 "R0402" R0402 3964.57,2464.57 r270 top
RE38 "R0402" R0402 4007.87,2464.57 r270 top
RE40 "R0402" R0402 4051.18,2464.57 r270 top
RN1 "R0402" R0402 1007.87,3322.83 r90 top
RN2 "R0402" R0402 881.89,3322.83 r90 top
RU1 "R0402" R0402 566.93,3283.46 r90 top
RU6 "R0402" R0402 661.42,2090.55 r180 top
RU7 "R0402" R0402 566.93,3196.85 r270 top
RU19 "R0402" R0402 263.78,2039.37 r180 top
RU22 "R0402" R0402 263.78,2007.87 r180 top
RU23 "R0402" R0402 224.41,2500 r90 top
RU24 "R0402" R0402 224.41,2582.68 r270 top
RU25 "R0402" R0402 185.04,2500 r270 top
RU108 "R0402" R0402 263.78,2165.35 r0 top
RU109 "R0402" R0402 263.78,2196.85 r0 top
RU110 "R0402" R0402 185.04,2582.68 r90 top
RU111 "R0402" R0402 263.78,2346.46 r0 top
RU112 "R0402" R0402 263.78,2314.96 r0 top
RU113 "R0402" R0402 263.78,2090.55 r0 top
RU114 "R0402" R0402 263.78,2122.05 r0 top
RU116 "R0402" R0402 263.78,2271.65 r0 top
RU119 "R0402" R0402 263.78,2240.16 r0 top
TP0 "BJ_LOGO" BJ_LOGO 4267.63,880.35 r90 top
TP3 "6X6" 6X6 3980,1140 r0 top
U2 "SOT23-6" SOT23-6 417.32,55.12 r180 top
U3 "SOT23-5" SOT23-5 653.54,3240.16 r180 top
U4 "SO8NB" SO8NB 4015.75,452.76 r180 top
U5 "SOT23" SOT23 2685.96,3199.96 r180 top
U6 "ESOP-8" ESOP-8 1744.4,3368.79 r0 top
U10 "SSOP16_SL2.1S" SSOP16_SL2.1S 578.74,1862.2 r0 top
U11 "MSOP-10" MSOP-10 842.52,1897.64 r0 top
U12 "SOT23-6" SOT23-6 811.02,59.06 r180 top
U13 "SOT23-6" SOT23-6 4354.33,1417.32 r90 top
U14 "UQFN-10_L2.0-W1.5-P0.50-BL" UQFN-10_L2.0-W1.5-P0.50-BL 566.93,2007.87 r270 top
U15 "QFN40" QFN40 4125.98,2688.98 r0 top
U16 "DFN2510-10_L2.5-W1.0-P0.50-BL" DFN2510-10_L2.5-W1.0-P0.50-BL 4889.76,881.89 r270 top
U17 "HDMIQ" HDMIQ 5062.99,870.08 r90 top
U18 "DFN2510-10_L2.5-W1.0-P0.50-BL" DFN2510-10_L2.5-W1.0-P0.50-BL 4889.76,763.78 r270 top
U28 "SOT23-5" SOT23-5 3118.11,2996.06 r90 top
U63 "SOT23-5" SOT23-5 4886.81,3448.82 r90 top
U64 "HELPERA733D-1" HELPERA733D-1 2720.47,1523.62 r90 top
UA1 "QFN40" QFN40 2322.04,3144.71 r0 top
USB4 "USB-A-3.0X2-90" USB-A-3.0X2-90 125.98,3125.98 r270 top
X1 "X3225" X3225 4484.25,2732.28 r270 top
X3 "X3225" X3225 480.31,1685.04 r0 top

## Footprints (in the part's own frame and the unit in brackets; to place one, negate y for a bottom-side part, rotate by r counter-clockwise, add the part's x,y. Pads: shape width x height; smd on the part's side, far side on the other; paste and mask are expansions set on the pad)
6X6 [mil]
  silkscreen extent 0,0 236,236
0805 [mm]
  rect 0.4x0.75 smd: 1(-0.4,-0.925) 2(0.4,-0.925) 3(0.4,0.925) 4(-0.4,0.925)
  silkscreen extent -1,-1.45 0.85,1
4018 [mm]
  rect 1.5x3.7 smd: 1(-1.5,0) 2(1.5,0)
  silkscreen extent -2.5,-2 2.5,2
BEEP_9042 [mm]
  oval 1.7x1.524 hole 0.8 slot 1.2 at 0 deg: 1(-2.5,0) 2(2.5,-0.13)
  silkscreen extent -4.5,-4.5 4.5,4.5
BJ_LOGO [mil]
  silkscreen extent -205,-203 191,187
C0402 [mm]
  rect 0.5x0.5 smd mask+0.05: 1(-0.425,0) 2(0.425,0)
  silkscreen extent -0.91,-0.43 0.91,0.43
C0603 [mm]
  rect 0.76x0.76 smd mask+0.05: 1(-0.71,0) 2(0.71,0)
  silkscreen extent -1.37,-0.71 1.37,0.71
C0805 [mil]
  rect 37x50 smd: 1(-40,0) 2(40,0)
  silkscreen extent -66,-32 66,32
D0603 [mil]
  rect 30x32 smd: 1(-30,0) 2(30,0)
  silkscreen extent -55,-25 55,25
D0805 [mil]
  rect 37x50 smd: 1(-40,0) 2(40,0)
  silkscreen extent -73,-36 75,36
DC470 [mm]
  oval 1.2x4 hole 0.6 slot 3.5 at 90 deg: 1(6.2,0)
  oval 1.2x3 hole 0.6 slot 2.5 at 90 deg: 2(0,0)
  oval 3x1.2 hole 0.6 slot 2.5 at 0 deg: 3(3.2,-4.7)
  silkscreen extent -7.7,-4.52 6.18,4.5
DFN2510-10_L2.5-W1.0-P0.50-BL [mm]
  rect 0.2x0.665 smd paste+0 mask+0.051: 1(-1,-0.433) 2(-0.5,-0.433) 4(0.5,-0.433) 5(1,-0.433) 6(1,0.433) 7(0.5,0.433) 9(-0.5,0.433) 10(-1,0.433)
  rect 0.4x0.665 smd paste+0.001 mask+0.051: 3(0,-0.433) 8(0,0.433)
  silkscreen extent -1.33,-1.11 1.33,0.58
DFN-3_2X2 [mm]
  rect 0.5x0.4 smd mask+0.05: 1(0.608,-0.65) 2(0.608,0.65)
  rect 1.3x1.6 smd: 3(-0.608,0)
  silkscreen extent -1.24,-1 1.2,1
DV [mm]
  round 5.2 hole 3.2: 1(0,0)
DVA [mm]
  round 3.3 hole 3.3 unplated: 1(0,0)
DVE [mm]
  round 3.6 hole 3.2: 1(0,0)
ESD0402 [mil]
  rect 24x20 smd: 1(-18,0) 2(18,0)
  silkscreen extent -36,-17 36,17
ESOP-8 [mil]
  oval 24x74 smd: 1(-75,-113) 2(-25,-113) 3(25,-113) 4(75,-113) 5(75,113) 6(25,113) 7(-25,113) 8(-75,113)
  rect 124x89 smd: 9(0,0)
  silkscreen extent -95,-65 95,65
F1812 [mm]
  rect 1.8x3.3 smd: 1(-2.349,0) 2(2.349,0)
  silkscreen extent -3.6,-2 3.6,2
FH35C-39S-0.3SHW [mm]
  rect 0.3x1.2 smd: 1(-5.7,-1.5) 2(-5.4,1.7) 3(-5.1,-1.5) 4(-4.8,1.7) 5(-4.5,-1.5) 6(-4.2,1.7) 7(-3.9,-1.5) 8(-3.6,1.7) 9(-3.3,-1.5) 10(-3,1.7) 11(-2.7,-1.5) 12(-2.4,1.7) 13(-2.1,-1.5) 14(-1.8,1.7) 15(-1.5,-1.5) 16(-1.2,1.7) 17(-0.9,-1.5) 18(-0.6,1.7) 19(-0.3,-1.5) 20(0,1.7) 21(0.3,-1.5) 22(0.6,1.7) 23(0.9,-1.5) 24(1.2,1.7) 25(1.5,-1.5) 26(1.8,1.7) 27(2.1,-1.5) 28(2.4,1.7) 29(2.7,-1.5) 30(3,1.7) 31(3.3,-1.5) 32(3.6,1.7) 33(3.9,-1.5) 34(4.2,1.7) 35(4.5,-1.5) 36(4.8,1.7) 37(5.1,-1.5) 38(5.4,1.7) 39(5.7,-1.5)
  rect 0.3x1.15 smd: 40(6.35,-1.062) 41(-6.35,-1.062)
  silkscreen extent -6.7,-2.94 6.7,2.43
FPC40-0.5MM-UP [mm]
  rect 0.3x1.5 smd: 1(19.5,-0.5) 2(19,-0.5) 3(18.5,-0.5) 4(18,-0.5) 5(17.5,-0.5) 6(17,-0.5) 7(16.5,-0.5) 8(16,-0.5) 9(15.5,-0.5) 10(15,-0.5) 11(14.5,-0.5) 12(14,-0.5) 13(13.5,-0.5) 14(13,-0.5) 15(12.5,-0.5) 16(12,-0.5) 17(11.5,-0.5) 18(11,-0.5) 19(10.5,-0.5) 20(10,-0.5) 21(9.5,-0.5) 22(9,-0.5) 23(8.5,-0.5) 24(8,-0.5) 25(7.5,-0.5) 26(7,-0.5) 27(6.5,-0.5) 28(6,-0.5) 29(5.5,-0.5) 30(5,-0.5) 31(4.5,-0.5) 32(4,-0.5) 33(3.5,-0.5) 34(3,-0.5) 35(2.5,-0.5) 36(2,-0.5) 37(1.5,-0.5) 38(1,-0.5) 39(0.5,-0.5) 40(0,-0.5)
  rect 1.8x3.8 smd: 41(-1.796,-3.345) 42(21.191,-3.35)
  silkscreen extent -2.71,-5.28 22.1,-0.63
FPC_0.5_6P_DOWN [mm]
  rect 0.3x1.25 smd: 1(0,0) 2(0.5,0) 3(1,0) 4(1.5,0) 5(2,0) 6(2.5,0)
  rrect0% 3x3 smd: 7(-2,2.3) 8(4.5,2.3)
  silkscreen extent -3.44,-0.93 5.93,4.9
HDMIQ [mm]
  rect 0.28x2.6 smd: 1(4.5,0) 2(4,0) 3(3.5,0) 4(3,0) 5(2.5,0) 6(2,0) 7(1.5,0) 8(1,0) 9(0.5,0) 10(0,0) 11(-0.5,0) 12(-1,0) 13(-1.5,0) 14(-2,0) 15(-2.5,0) 16(-3,0) 17(-3.5,0) 18(-4,0) 19(-4.5,0)
  oval 1.5x3.3 hole 1.016 slot 2.286 at 90 deg: 20(-7.25,-0.76) 21(7.25,-0.76)
  oval 1.5x2.616 hole 1.016 slot 1.778 at 90 deg: 22(-7.25,-6.72) 23(7.26,-6.732)
  silkscreen extent -8.3,-11.41 8.3,1.39
HDR2X20$2F$2.0 [mil]
  rect 60x60 hole 32: 1(0,0)
  round 60 hole 32: 2(0,78.74) 3(78.74,0) 4(78.74,78.74) 5(157.48,0) 6(157.48,78.74) 7(236.22,0) 8(236.22,78.74) 9(314.96,0) 10(314.96,78.74) 11(393.7,0) 12(393.7,78.74) 13(472.44,0) 14(472.44,78.74) 15(551.18,0) 16(551.18,78.74) 17(629.92,0) 18(629.92,78.74) 19(708.66,0) 20(708.66,78.74) 21(787.4,0) 22(787.4,78.74) 23(866.14,0) 24(866.14,78.74) 25(944.88,0) 26(944.88,78.74) 27(1023.62,0) 28(1023.62,78.74) 29(1102.36,0) 30(1102.36,78.74) 31(1181.1,0) 32(1181.1,78.74) 33(1259.84,0) 34(1259.84,78.74) 35(1338.58,0) 36(1338.58,78.74) 37(1417.32,0) 38(1417.32,78.74) 39(1496.06,0) 40(1496.06,78.74)
  silkscreen extent -188,-95 1684,148
HELPERA733D-1 [mm]
  oval 1x0.6 smd: 1(-30,18) 2(-30,17) 3(-30,16) 4(-30,15) 5(-30,14) 6(-30,13) 7(-30,12) 8(-30,11) 9(-30,10) 10(-30,9) 11(-30,8) 12(-30,7) 13(-30,6) 14(-30,5) 15(-30,4) 16(-30,3) 17(-30,2) 18(-30,1) 19(-30,0) 20(-30,-1) 21(-30,-2) 22(-30,-3) 23(-30,-4) 24(-30,-5) 25(-30,-6) 26(-30,-7) 27(-30,-8) 28(-30,-9) 29(-30,-10) 30(-30,-11) 31(-30,-12) 32(-30,-13) 33(-30,-14) 34(-30,-15) 35(-30,-16) 36(-30,-17) 37(-30,-18) 95(30,-18) 96(30,-17) 97(30,-16) 98(30,-15) 99(30,-14) 100(30,-13) 101(30,-12) 102(30,-11) 103(30,-10) 104(30,-9) 105(30,-8) 106(30,-7) 107(30,-6) 108(30,-5) 109(30,-4) 110(30,-3) 111(30,-2) 112(30,-1) 113(30,0) 114(30,1) 115(30,2) 116(30,3) 117(30,4) 118(30,5) 119(30,6) 120(30,7) 121(30,8) 122(30,9) 123(30,10) 124(30,11) 125(30,12) 126(30,13) 127(30,14) 128(30,15) 129(30,16) 130(30,17) 131(30,18)
  oval 0.6x1 smd: 38(-28,-20) 39(-27,-20) 40(-26,-20) 41(-25,-20) 42(-24,-20) 43(-23,-20) 44(-22,-20) 45(-21,-20) 46(-20,-20) 47(-19,-20) 48(-18,-20) 49(-17,-20) 50(-16,-20) 51(-15,-20) 52(-14,-20) 53(-13,-20) 54(-12,-20) 55(-11,-20) 56(-10,-20) 57(-9,-20) 58(-8,-20) 59(-7,-20) 60(-6,-20) 61(-5,-20) 62(-4,-20) 63(-3,-20) 64(-2,-20) 65(-1,-20) 66(0,-20) 67(1,-20) 68(2,-20) 69(3,-20) 70(4,-20) 71(5,-20) 72(6,-20) 73(7,-20) 74(8,-20) 75(9,-20) 76(10,-20) 77(11,-20) 78(12,-20) 79(13,-20) 80(14,-20) 81(15,-20) 82(16,-20) 83(17,-20) 84(18,-20) 85(19,-20) 86(20,-20) 87(21,-20) 88(22,-20) 89(23,-20) 90(24,-20) 91(25,-20) 92(26,-20) 93(27,-20) 94(28,-20) 132(28,20) 133(27,20) 134(26,20) 135(25,20) 136(24,20) 137(23,20) 138(22,20) 139(21,20) 140(20,20) 141(19,20) 142(18,20) 143(17,20) 144(16,20) 145(15,20) 146(14,20) 147(13,20) 148(12,20) 149(11,20) 150(10,20) 151(9,20) 152(8,20) 153(7,20) 154(6,20) 155(5,20) 156(4,20) 157(3,20) 158(2,20) 159(1,20) 160(0,20) 161(-1,20) 162(-2,20) 163(-3,20) 164(-4,20) 165(-5,20) 166(-6,20) 167(-7,20) 168(-8,20) 169(-9,20) 170(-10,20) 171(-11,20) 172(-12,20) 173(-13,20) 174(-14,20) 175(-15,20) 176(-16,20) 177(-17,20) 178(-18,20) 179(-19,20) 180(-20,20) 181(-21,20) 182(-22,20) 183(-23,20) 184(-24,20) 185(-25,20) 186(-26,20) 187(-27,20) 188(-28,20)
  silkscreen extent -31.1,-21.1 31.1,21.1
HY911130A [mil]
  round 60 hole 35: 1(0,0) 2(-50.39,100) 3(-100,0) 4(-150.39,100) 5(-200,0) 6(-250.39,100) 7(-300,0) 8(-350.39,100) 9(-400,0) 10(-450.39,100) 13(-377.56,542.91) 14(-477.56,542.91)
  round 60 hole 40.16: 11(44.09,542.91) 12(-55.91,542.91)
  round 88.58 / inner round 78.74 / far side round 78.74 hole 64.17: 15(79.92,229.92) 16(-529.92,229.92)
  round 127.95 hole 127.95: 17(0,350) 18(-450,350)
  silkscreen extent -542,-76 92,780
KEY_3X4 [mm]
  rect 2x1.35 smd: 1(-2,0) 2(2,0)
  silkscreen extent -2,-1.5 2,1.5
L0603 [mm]
  rect 1x0.8 smd: 1(0.025,0.025) 2(1.525,0.025)
  silkscreen extent -0.62,-0.72 2.18,0.78
MARK [mil]
  round 40 all layers, no hole: 1(0,0)
MIC6050 [mm]
  round 1.2 hole 0.6: 1(1,-1) 2(1,1)
  silkscreen extent -3.1,-3.1 3.1,3.1
MINI_PCIEX1-52P-5.2H [mm]
  rect 0.61x2.007 smd: 1(-11.8,-30.775) 2(-11.4,-21.575) 3(-11,-30.775) 4(-10.6,-21.575) 5(-10.2,-30.775) 6(-9.8,-21.575) 7(-9.4,-30.775) 8(-9,-21.575) 9(-8.6,-30.775) 10(-8.2,-21.575) 11(-7.8,-30.775) 12(-7.4,-21.575) 13(-7,-30.775) 14(-6.6,-21.575) 15(-6.2,-30.775) 16(-5.8,-21.575) 17(-2.2,-30.775) 18(-1.8,-21.575) 19(-1.4,-30.775) 20(-1,-21.575) 21(-0.6,-30.775) 22(-0.2,-21.575) 23(0.2,-30.775) 24(0.6,-21.575) 25(1,-30.775) 26(1.4,-21.575) 27(1.8,-30.775) 28(2.2,-21.575) 29(2.6,-30.775) 30(3,-21.575) 31(3.4,-30.775) 32(3.8,-21.575) 33(4.2,-30.775) 34(4.6,-21.575) 35(5,-30.775) 36(5.4,-21.575) 37(5.8,-30.775) 38(6.2,-21.575) 39(6.6,-30.775) 40(7,-21.575) 41(7.4,-30.775) 42(7.8,-21.575) 43(8.2,-30.775) 44(8.6,-21.575) 45(9,-30.775) 46(9.4,-21.575) 47(9.8,-30.775) 48(10.2,-21.575) 49(10.6,-30.775) 50(11,-21.575) 51(11.4,-30.775) 52(11.8,-21.575)
  rect 4x4 / inner round 4 / far side rect 4x4 hole 2.3: _/2(-12.1,21.875) _/3(12.1,21.875)
  round 1.6 hole 1.6: G1(-12.5,-26.175)
  round 1.092 hole 1.092: G2(12.5,-26.175)
  rect 2.311x3.2 smd: M1(-14.65,-30.175) M2(14.65,-30.175)
  silkscreen extent -15,-30.27 15,24.78
MSOP-10 [mm]
  oval 1.2x0.25 smd paste-0.1 mask-0.1: 1(-2.55,1) 2(-2.55,0.5) 3(-2.55,0) 4(-2.55,-0.5) 5(-2.55,-1) 6(2.55,-1) 7(2.55,-0.5) 8(2.55,0) 9(2.55,0.5) 10(2.55,1)
  silkscreen extent -3.2,-1.8 3.2,1.8
MX1.25-2P [mil]
  oval 30x60 hole 19.68: 1(-24.61,0) 2(24.61,0)
  silkscreen extent -85,-85 85,47
NANO-SIM-7P [mm]
  rect 0.8x1.23 smd: 1(0.23,6.9) 2(-2.31,6.9) 3(-4.85,6.9) 5(1.5,6.9) 6(-1.04,6.9) 7(-3.58,6.9)
  rect 0.65x1.23 smd: 4(2.45,6.9)
  rect 0.7x2 smd: 8(-6.52,5.3) 9(6.48,5.3) 10(-6.52,-6.3) 11(6.48,-6.3)
  round 0.75 hole 0.75 unplated: 12(-5.02,-5.449) 13(3.48,-5.449)
  silkscreen extent -7.1,-9.3 7,7.7
PH-2.0-2P [mil]
  round 60 hole 35: 1(0,0) 2(78.74,0)
  silkscreen extent -79,-67 157,114
PH-2.0-4P [mil]
  round 60 hole 35: 1(0,0) 2(78.74,0) 3(157.48,0) 4(236.22,0)
  silkscreen extent -79,-67 315,114
PJ327F [mm]
  rect 2x3 smd paste+0.3: 1(2.1,-0.5) 2(7.4,-0.5) 3(9.8,6.5) 4(5.51,6.5) 5(2.11,6.5)
  round 1.5 hole 1.5 unplated: 6(9,3) 7(3,3)
  silkscreen extent -1.91,-0.2 12,6.2
QFN40 [mm]
  rect 0.2x0.8 smd paste+0.05: 1(1.8,2.55) 2(1.4,2.55) 3(1,2.55) 4(0.6,2.55) 5(0.2,2.55) 6(-0.2,2.55) 7(-0.6,2.55) 8(-1,2.55) 9(-1.4,2.55) 10(-1.8,2.55) 21(-1.8,-2.55) 22(-1.4,-2.55) 23(-1,-2.55) 24(-0.6,-2.55) 25(-0.2,-2.55) 26(0.2,-2.55) 27(0.6,-2.55) 28(1,-2.55) 29(1.4,-2.55) 30(1.8,-2.55)
  rect 0.8x0.2 smd paste+0.05: 11(-2.55,1.8) 12(-2.55,1.4) 13(-2.55,1) 14(-2.55,0.6) 15(-2.55,0.2) 16(-2.55,-0.2) 17(-2.55,-0.6) 18(-2.55,-1) 19(-2.55,-1.4) 20(-2.55,-1.8) 31(2.55,-1.8) 32(2.55,-1.4) 33(2.55,-1) 34(2.55,-0.6) 35(2.55,-0.2) 36(2.55,0.2) 37(2.55,0.6) 38(2.55,1) 39(2.55,1.4) 40(2.55,1.8)
  rrect0% 3x3 smd: 41(0,0)
  silkscreen extent -3.2,-3.2 3.2,3.2
R0402 [mm]
  rect 0.5x0.5 smd mask+0.05: 1(-0.425,0) 2(0.425,0)
  silkscreen extent -0.9,-0.4 0.9,0.4
R0805 [mil]
  rect 37x50 smd: 1(-40,0) 2(40,0)
  silkscreen extent -66,-32 66,32
RB.1$2F$.3 [mm]
  oval 1.8x2.2 hole 0.66 slot 1.4 at 0 deg: 1(1.27,0) 2(-1.27,0)
  silkscreen extent -4.06,-4.06 4.06,4.06
RCLAMP0524P [mm]
  rect 0.2x0.675 smd: 1(1.05,0.435) 2(0.55,0.435) 4(-0.55,0.435) 5(-1.05,0.435) 6(-1.05,-0.44) 7(-0.55,-0.44) 9(0.55,-0.44) 10(1.05,-0.44)
  rect 0.4x0.675 smd: 3(-0.05,0.435) 8(-0.05,-0.44)
  silkscreen extent -1.22,-0.85 1.22,0.85
SML2520_1P2H$2F$4 [mil]
  rect 78.74x31.5 smd: 1(0,-39.35) 2(0,39.35)
  silkscreen extent -47,-59 47,59
SO8NB [mil]
  oval 24x74 smd: 1(-75,-113) 2(-25,-113) 3(25,-113) 4(75,-113) 5(75,113) 6(25,113) 7(-25,113) 8(-75,113)
  silkscreen extent -95,-65 95,65
SOD123 [mil]
  rrect0% 40x40 smd: 1(-69,0) 2(69,0)
  silkscreen extent -97,-39 97,39
SOD323 [mil]
  rect 37x50 smd: 1(-40,0) 2(40,0)
  silkscreen extent -73,-36 75,36
SOT23 [mil]
  rect 36x36 smd: 1(-37.5,-39) 2(37.5,-39)
  rect 36x50 smd: 3(0,41)
  silkscreen extent -55,-50 55,40
SOT23-5 [mm]
  rect 0.5x1.2 smd: 1(-0.95,-1.4) 2(0,-1.4) 3(0.95,-1.4) 4(0.95,1.4) 5(-0.95,1.4)
  silkscreen extent -1.45,-0.95 1.45,0.95
SOT23-6 [mm]
  rect 0.5x1.2 smd: 1(-0.95,-1.4) 2(0,-1.4) 3(0.95,-1.4) 4(0.95,1.4) 5(0,1.4) 6(-0.95,1.4)
  silkscreen extent -1.45,-0.95 1.45,0.95
SS-12F44(1P2T) [mm]
  oval 1.524x2 hole 0.6 slot 1 at 0 deg: 1(-3,0) 2(0,0) 3(3,0)
  oval 1.7x2.8 hole 0.7 slot 1.8 at 90 deg: 4(-6,0) 5(6,0)
  silkscreen extent -6,-3 6,3
SSOP16_SL2.1S [mm]
  oval 1x0.2 smd: 1(-1.9,1.855) 2(-1.9,1.325) 3(-1.9,0.795) 4(-1.9,0.265) 5(-1.9,-0.265) 6(-1.9,-0.795) 7(-1.9,-1.325) 8(-1.9,-1.855) 9(1.9,-1.855) 10(1.9,-1.325) 11(1.9,-0.795) 12(1.9,-0.265) 13(1.9,0.265) 14(1.9,0.795) 15(1.9,1.325) 16(1.9,1.855)
  silkscreen extent -1.2,-2.2 1.2,2.2
SW-TH-DSWB03LHGET [mm]
  round 1.6 hole 1: 1(-2.54,3.81) 2(0,3.81) 3(2.54,3.81) 4(-2.54,-3.81) 5(0,-3.81) 6(2.54,-3.81)
  silkscreen extent -4.6,-4.8 4.6,4.8
TF_PUSH1 [mm]
  rect 0.7x1.6 smd: 1(-2.25,-7.25) 2(-1.15,-7.25) 3(-0.05,-7.25) 4(1.05,-7.25) 5(2.15,-7.25) 6(3.25,-7.25) 7(4.35,-7.25) 8(5.45,-7.25) 9(6.55,-7.25)
  rrect0% 1.5x1.5 smd: 10(-6.85,-6.75)
  rect 1.2x1.4 smd: 11(7.75,-6.75)
  rect 1.2x2.2 smd: 12(7.75,2.85) 13(-7.75,2.85)
  round 1 hole 1: _(4.95,3.25) _/2(-3.05,3.25)
  silkscreen extent -7.55,-7.53 7.55,10.1
UQFN-10_L2.0-W1.5-P0.50-BL [mm]
  rect 0.25x0.525 smd: 1(-0.75,-0.675) 2(-0.25,-0.675) 3(0.25,-0.675) 4(0.75,-0.675) 6(0.75,0.675) 7(0.25,0.675) 8(-0.25,0.675) 9(-0.75,0.675)
  rect 0.58x0.3 smd: 5(0.86,0) 10(-0.86,0)
  silkscreen extent -1.1,-1.51 1.1,0.85
USB-A-3.0X2-90 [mm]
  round 1.1 hole 0.7 mask+0.05: 1(-3.5,-1.35) 2(-1,-1.35) 3(1,-1.35) 4(3.5,-1.35) 5(4,0.15) 6(2,0.15) 7(0,0.15) 8(-2,0.15) 9(-4,0.15) 10(-3.5,1.85) 11(-1,1.85) 12(1,1.85) 13(3.5,1.85) 14(4,3.35) 15(2,3.35) 16(0,3.35) 17(-2,3.35) 18(-4,3.35)
  round 3.2 hole 2.4 mask+0.05: 19(6.57,-3.35) 20(6.57,2.33) 21(-6.57,2.33) 22(-6.57,-3.35)
  silkscreen extent -7.26,-12.97 7.19,4.7
USB-C-SMD-24P [mm]
  oval 1.8x2.2 hole 1.3 slot 1.6 at 90 deg: 1(-4.191,1.905) 4(4.191,1.905)
  oval 1.2x2.4 hole 0.6 slot 1.9 at 90 deg: 2(-4.32,-2.625) 3(4.32,-2.625)
  round 0.65 hole 0.65: 5(-3.399,0.575) 6(3.404,0.576)
  rect 0.3x1 smd paste+0.025: A1(-2.625,2.625) A2(-2.125,2.625) A3(-1.625,2.625) A4(-1.125,2.625) A5(-0.625,2.625) A6(-0.125,2.625) A7(0.375,2.625) A8(0.875,2.625) A9(1.375,2.625) A10(1.875,2.625) A11(2.375,2.625) A12(2.875,2.625) B1(2.625,1.275) B2(2.125,1.275) B3(1.625,1.275) B4(1.125,1.275) B5(0.625,1.275) B6(0.125,1.275) B7(-0.375,1.275) B8(-0.875,1.275) B9(-1.375,1.275) B10(-1.875,1.275) B11(-2.375,1.275) B12(-2.875,1.275)
  silkscreen extent -4.5,-5.33 4.5,2.68
X3225 [mm]
  rect 1.4x1.2 smd: 1(-1.2,-0.85) 2(1.2,-0.85) 3(1.2,0.85) 4(-1.2,0.85)
  silkscreen extent -2.06,-1.58 2.08,1.58
XH-2.54-2P [mil]
  rect 60x60 / inner round 60 / far side rect 60x60 hole 37: 1(0,0)
  round 60 hole 37: 2(100,0)
  silkscreen extent -100,-98 200,138
XH-2.54-4P [mil]
  rect 60x60 hole 37: 1(150,0)
  round 60 hole 37: 2(50,0) 3(-50,0) 4(-150,0)
  silkscreen extent -245,-138 245,98
XH-2.54-7P [mil]
  rect 60x60 hole 37: 1(300,0)
  round 60 hole 37: 2(200,0) 3(100,0) 4(0,0) 5(-100,0) 6(-200,0) 7(-300,0)
  silkscreen extent -394,-138 394,98

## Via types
v1: diameter 22, hole 12, Top to Bottom, 1667 vias

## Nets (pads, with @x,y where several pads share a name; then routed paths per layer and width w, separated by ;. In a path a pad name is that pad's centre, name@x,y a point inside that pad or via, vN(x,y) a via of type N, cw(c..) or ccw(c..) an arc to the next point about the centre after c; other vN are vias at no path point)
3V3-EN: R37.2 U28.1 U64.173 | length 3058.9
  Top w6: U64.173@1933.07,1011.81 1950.08,1011.81 1977.28,1039.01 2077.47,1039.01 2222.28,1183.82 2222.28,2414.25 2202.65,2433.88 2202.65,2469.86 v1(2223.89,2491.1) ; v1(2655.59,2561.58) 2663.62,2569.61 3173.14,2569.61 v1(3171.79,2569.88) ; U28.1@3173.23,2958.66 3174.21,2957.68 R37.2@3174.21,2913.39 3174.21,2858.25 v1(3174.39,2858.07)
  Bottom w6: v1(2223.89,2491.1) 2231.87,2491.24 2585.25,2491.24 v1(2655.59,2561.58) ; v1(3171.79,2569.88) 3173.13,2569.88 3173.13,2856.81 v1(3174.39,2858.07)
4G-EN-PL12: R292.1 U12.4 U64.171 | length 2722
  Top w6: U12.4@773.62,3.94 772.64,2.95 R292.1@716.54,2.95 680,-33.58 680,-184 691.14,-195.14 1469.3,-195.14 1484.21,-180.23 1484.21,309.06 1558.3,383.15 1820.96,383.15 1846.63,408.8 1846.63,1067.1 1869.87,1090.35 U64.171@1933.07,1090.55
